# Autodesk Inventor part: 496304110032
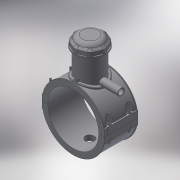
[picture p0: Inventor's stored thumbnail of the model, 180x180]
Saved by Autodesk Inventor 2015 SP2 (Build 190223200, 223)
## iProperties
Created: 2017-07
Part Number: 496304110032
Material: Generic
Description: PLASSON TAPPING SADDLE 110x32
Document SubType Name: Modeling
Designer: KIM
Mass: 705.488 g
Surface Area: 1726.91 cm^2
Volume: 705.488 cm^3
Density: 1 g/cm^3
Appearance: Default
Author: KIM
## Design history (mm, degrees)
derived "496304.ipt"
feature "Solid1::496304.ipt"
feature "Solid2::496304.ipt"
feature "Solid4::496304.ipt"
feature "Solid5::496304.ipt"
tag "TaggingFeature1"
body "Solid1"
body "Solid2"
other parameters: "d2" = 148, "d3" = 27.5, "d4" = 118, "d5" = 0, "d6" = 0.1, "d8" = 0, "d19" = 6, "d20" = 6, "d21" = 70.8, "d23" = 0, "d24" = 35.4, "d26" = 0, "d29" = 3, "d30" = 36.66667, "d31" = 6, "d32" = 0, "d33" = 0, "d34" = 0.6, "d40" = 68.64, "d41" = 66, "d43" = 0, "d45" = 0, "d47" = 136.8, "d70" = 15, "d72" = 0, "d73" = 6, "d75" = 5, "d76" = 0, "d77" = 5.5, "d78" = 85, "d79" = 15, "d80" = 47.2, "d82" = 5 deg, "d84" = 4, "d85" = 14, "d86" = 0, "d87" = 3, "d88" = 0, "d89" = 1, "d90" = 1, "d91" = 94.4, "d92" = 0, "d93" = 0.5, "d94" = 57.89474, "d96" = 134.64, "d97" = 2.36, "d98" = 0, "d102" = 1.1, "d120" = 140 deg, "d121" = 24.228, "d122" = 20 deg, "d123" = 264, "d124" = 79.2, "d126" = 0, "d143" = 113.3, "d145" = 16.92308, "d149" = 1.65, "d150" = 18.61538, "d153" = 118, "d154" = 0, "d156" = 66, "d157" = 160 deg, "d159" = 4.4, "d161" = 1.65, "d162" = 70.8, "d163" = 0, "d164" = 55, "d167" = 11, "d168" = 64.39024, "d170" = 3.375, "d172" = 0, "d173" = 1, "d175" = 55, "d176" = 20 deg, "d177" = 7.7, "d178" = 22, "d180" = 0, "d183" = 8.8, "d184" = 6.16, "d185" = 38.35, "d186" = 38.35, "d187" = 66, "d188" = 6.6, "d189" = 7.7, "d190" = 0, "d191" = 99, "d193" = 6.3, "d194" = 4.13, "d195" = 90 deg, "d197" = 0, "d199" = 0, "d200" = 11, "d202" = 0, "d203" = 114, "d204" = 62.7, "d205" = 46.2, "d206" = 56.1, "d207" = 85.5, "d208" = 88.92, "d209" = 106.02, "d210" = 56.76, "d211" = 66, "d212" = 52.8, "d213" = 0, "d216" = 0, "d217" = 11, "d218" = 11, "d219" = 2.2, "d224" = 0, "d230" = 4.4, "d233" = 6, "d236" = 74, "d237" = 35.4, "d238" = 6.02433, "d240" = 35.4, "d241" = 35.4, "d242" = 35.4, "d243" = 6, "d244" = 35.4, "d245" = 35.4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
